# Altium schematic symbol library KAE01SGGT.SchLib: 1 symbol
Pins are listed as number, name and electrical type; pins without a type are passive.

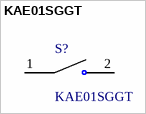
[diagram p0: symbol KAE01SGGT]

## KAE01SGGT
designator S?
Dip Switch SPST 1 Position Surface Mount Slide (Standard) Actuator 25mA 24VDC; MF: E-Switch
footprint *SW_KAE01SGGT
pins: 1, 2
